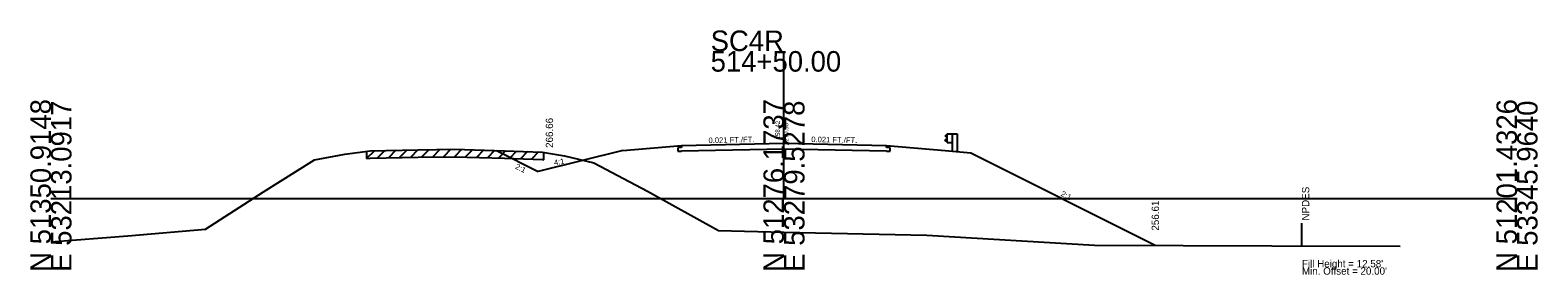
# Model space of a CAD drawing. Extents: x 7498 to 13027, y 90095 to 109625.
# Drawn here: x 8521.2 to 8726.8, y 104594.8 to 104628.1 of the extents above; entities that cross this region are included whole.
import ezdxf

# ---------------------------------------------------------------- set-up
doc = ezdxf.new("R2010")
doc.units = 0
for name, color, linetype in [('Level 10', 7, 'Continuous'), ('Level 11', 7, 'Continuous'), ('Level 12', 7, 'Continuous'), ('Level 24', 7, 'Continuous'), ('Level 32', 7, 'Continuous'), ('Level 33', 7, 'Continuous'), ('Level 50', 7, 'Continuous'), ('Level 55', 7, 'Continuous'), ('Level 59', 7, 'Continuous'), ('Level 6', 7, 'Continuous'), ('Level 60', 7, 'Continuous'), ('Level 61', 7, 'Continuous'), ('Level 63', 7, 'Continuous'), ('Level 7', 7, 'Continuous')]:
    doc.layers.add(name, color=color, linetype=linetype)

msp = doc.modelspace()

# ---------------------------------------------------------------- linework, layer by layer
at = {"layer": 'Level 11'}
for p, q in [((8609.99, 104612.07), (8609.49, 104612.05)), ((8609.49, 104612.05), (8609.49, 104611.57)), ((8609.99, 104612.37), (8609.99, 104612.07)), ((8637.99, 104612.07), (8637.99, 104612.37)), ((8638.49, 104612.05), (8637.99, 104612.07)), ((8638.49, 104611.57), (8638.49, 104612.05)), ((8609.49, 104611.57), (8609.99, 104611.59)), ((8637.99, 104611.59), (8638.49, 104611.57))]:
    msp.add_line(p, q, dxfattribs=at)
at = {"layer": 'Level 12'}
for p, q in [((8623.99, 104611.88), (8609.99, 104611.59)), ((8637.99, 104611.59), (8623.99, 104611.88))]:
    msp.add_line(p, q, dxfattribs=at)
at = {"layer": 'Level 24'}
for p, q in [((8646.26, 104613.88), (8645.99, 104613.68)), ((8646.26, 104612.78), (8646.26, 104613.95)), ((8646.26, 104613.95), (8646.93, 104613.95)), ((8646.93, 104613.95), (8646.93, 104611.6)), ((8646.93, 104613.95), (8647.6, 104613.95)), ((8647.6, 104613.95), (8647.6, 104611.54)), ((8645.99, 104613.68), (8645.99, 104613.63)), ((8645.99, 104613.63), (8646.26, 104613.43)), ((8645.99, 104613.1), (8646.26, 104613.3)), ((8645.99, 104613.05), (8645.99, 104613.1)), ((8646.26, 104612.85), (8645.99, 104613.05)), ((8646.26, 104612.78), (8646.93, 104612.78))]:
    msp.add_line(p, q, dxfattribs=at)
at = {"layer": 'Level 55'}
msp.add_line((8694.65, 104598.77), (8694.65, 104601.77), dxfattribs=at)
at = {"layer": 'Level 59'}
for p, q in [((8609.99, 104612.37), (8623.99, 104612.66)), ((8623.99, 104612.66), (8637.99, 104612.37))]:
    msp.add_line(p, q, dxfattribs=at)
at = {"layer": 'Level 6'}
for p, q in [((8601.99, 104611.7), (8609.99, 104612.37)), ((8637.99, 104612.37), (8645.99, 104611.7)), ((8645.99, 104611.7), (8649.49, 104611.35))]:
    msp.add_line(p, q, dxfattribs=at)
at = {"layer": 'Level 60'}
for p, q in [((8567.53, 104611.64), (8574.08, 104611.76)), ((8574.08, 104611.76), (8579.04, 104611.84)), ((8579.04, 104611.84), (8585.87, 104611.62)), ((8552.99, 104606.03), (8559.96, 104610.39)), ((8559.96, 104610.39), (8564.08, 104611.18)), ((8564.08, 104611.18), (8567.53, 104611.64)), ((8585.87, 104611.62), (8591.04, 104611.46)), ((8591.04, 104611.46), (8594.03, 104610.94)), ((8594.03, 104610.94), (8598.07, 104610)), ((8598.07, 104610), (8605.37, 104606.14)), ((8545.09, 104600.95), (8552.99, 104606.03)), ((8605.37, 104606.14), (8615.07, 104600.78)), ((8523.99, 104599.26), (8534.48, 104600.06)), ((8534.48, 104600.06), (8545.09, 104600.95)), ((8615.07, 104600.78), (8623.99, 104600.58)), ((8623.99, 104600.58), (8643.49, 104600.15)), ((8643.49, 104600.15), (8666.37, 104598.81)), ((8666.37, 104598.81), (8690.55, 104598.69)), ((8690.55, 104598.69), (8708.06, 104598.64))]:
    msp.add_line(p, q, dxfattribs=at)
at = {"layer": 'Level 61'}
for p, q in [((8569.56, 104611.68), (8568.54, 104610.66)), ((8571.06, 104611.71), (8570.04, 104610.69)), ((8572.56, 104611.73), (8571.54, 104610.71)), ((8574.06, 104611.76), (8573.04, 104610.74)), ((8575.56, 104611.78), (8574.54, 104610.77)), ((8577.06, 104611.81), (8576.04, 104610.79)), ((8578.56, 104611.84), (8577.54, 104610.82)), ((8580.01, 104611.81), (8579.04, 104610.84)), ((8581.51, 104611.76), (8580.54, 104610.8)), ((8583.01, 104611.72), (8582.04, 104610.75)), ((8584.51, 104611.67), (8583.54, 104610.7)), ((8568.12, 104611.65), (8567.04, 104610.58)), ((8567.04, 104611.58), (8567.04, 104610.58)), ((8567.04, 104610.58), (8567.53, 104610.64)), ((8567.53, 104610.64), (8574.08, 104610.76)), ((8574.08, 104610.76), (8579.04, 104610.84)), ((8579.04, 104610.84), (8585.87, 104610.62)), ((8586.01, 104611.62), (8585.04, 104610.65)), ((8585.87, 104610.62), (8591.04, 104610.46)), ((8587.51, 104611.57), (8586.54, 104610.6)), ((8589.01, 104611.53), (8588.04, 104610.56)), ((8590.51, 104611.48), (8589.54, 104610.51)), ((8591.04, 104610.46), (8591.25, 104610.43)), ((8591.25, 104610.43), (8591.25, 104611.43))]:
    msp.add_line(p, q, dxfattribs=at)
at = {"layer": 'Level 63'}
for p, q in [((8623.99, 104605.16), (8623.99, 104625.22)), ((8523.99, 104605.16), (8623.99, 104605.16)), ((8623.99, 104605.16), (8723.99, 104605.16))]:
    msp.add_line(p, q, dxfattribs=at)
at = {"layer": 'Level 7'}
for p, q in [((8584.75, 104611.66), (8590.45, 104608.81)), ((8601.99, 104611.7), (8590.45, 104608.81)), ((8649.49, 104611.35), (8674.65, 104598.77))]:
    msp.add_line(p, q, dxfattribs=at)

# ---------------------------------------------------------------- texts
at = {"layer": 'Level 10'}
msp.add_text('258.42', height=0.6, rotation=90, dxfattribs=at).set_placement((8623.43, 104613.19))
at = {"layer": 'Level 32'}
for s, rotation, p in [('0.021 FT./FT.', 1.1916, (8613.7, 104612.69)), ('0.021 FT./FT.', 358.8084, (8627.71, 104612.83)), ('2:1', 333.435, (8587.27, 104609.25)), ('4:1', 9.4623, (8592.67, 104609.65)), ('2:1', 333.435, (8661.68, 104605.54))]:
    msp.add_text(s, height=0.75, rotation=rotation, dxfattribs=at).set_placement(p)
at = {"layer": 'Level 33'}
for s, p in [('266.66', (8592.49, 104612.03)), ('256.61', (8675.15, 104600.77))]:
    msp.add_text(s, height=1, rotation=90, dxfattribs=at).set_placement(p)
at = {"layer": 'Level 50'}
msp.add_text(' NPDES', height=1, rotation=90, dxfattribs=at).set_placement((8695.65, 104601.77))
for s, p in [("Fill Height = 12.58' ", (8694.65, 104595.77)), ("Min. Offset = 20.00' ", (8694.65, 104594.77))]:
    msp.add_text(s, height=1, dxfattribs=at).set_placement(p)
at = {"layer": 'Level 59'}
msp.add_text(' 270.50', height=0.6, rotation=90, dxfattribs=at).set_placement((8624.59, 104612.66))
at = {"layer": 'Level 63'}
for s, p in [('SC4R', (8613.99, 104625.22)), ('514+50.00', (8613.99, 104622.42))]:
    msp.add_text(s, height=2.8, dxfattribs=at).set_placement(p)
for s, p in [('N 51350.9148', (8523.99, 104595.16)), ('E 53213.0917', (8526.79, 104595.16)), ('N 51276.1737', (8623.99, 104595.16)), ('E 53279.5278', (8626.79, 104595.16)), ('N 51201.4326', (8723.99, 104595.16)), ('E 53345.9640', (8726.79, 104595.16))]:
    msp.add_text(s, height=2.8, rotation=90, dxfattribs=at).set_placement(p)

doc.saveas('drawing.dxf')
